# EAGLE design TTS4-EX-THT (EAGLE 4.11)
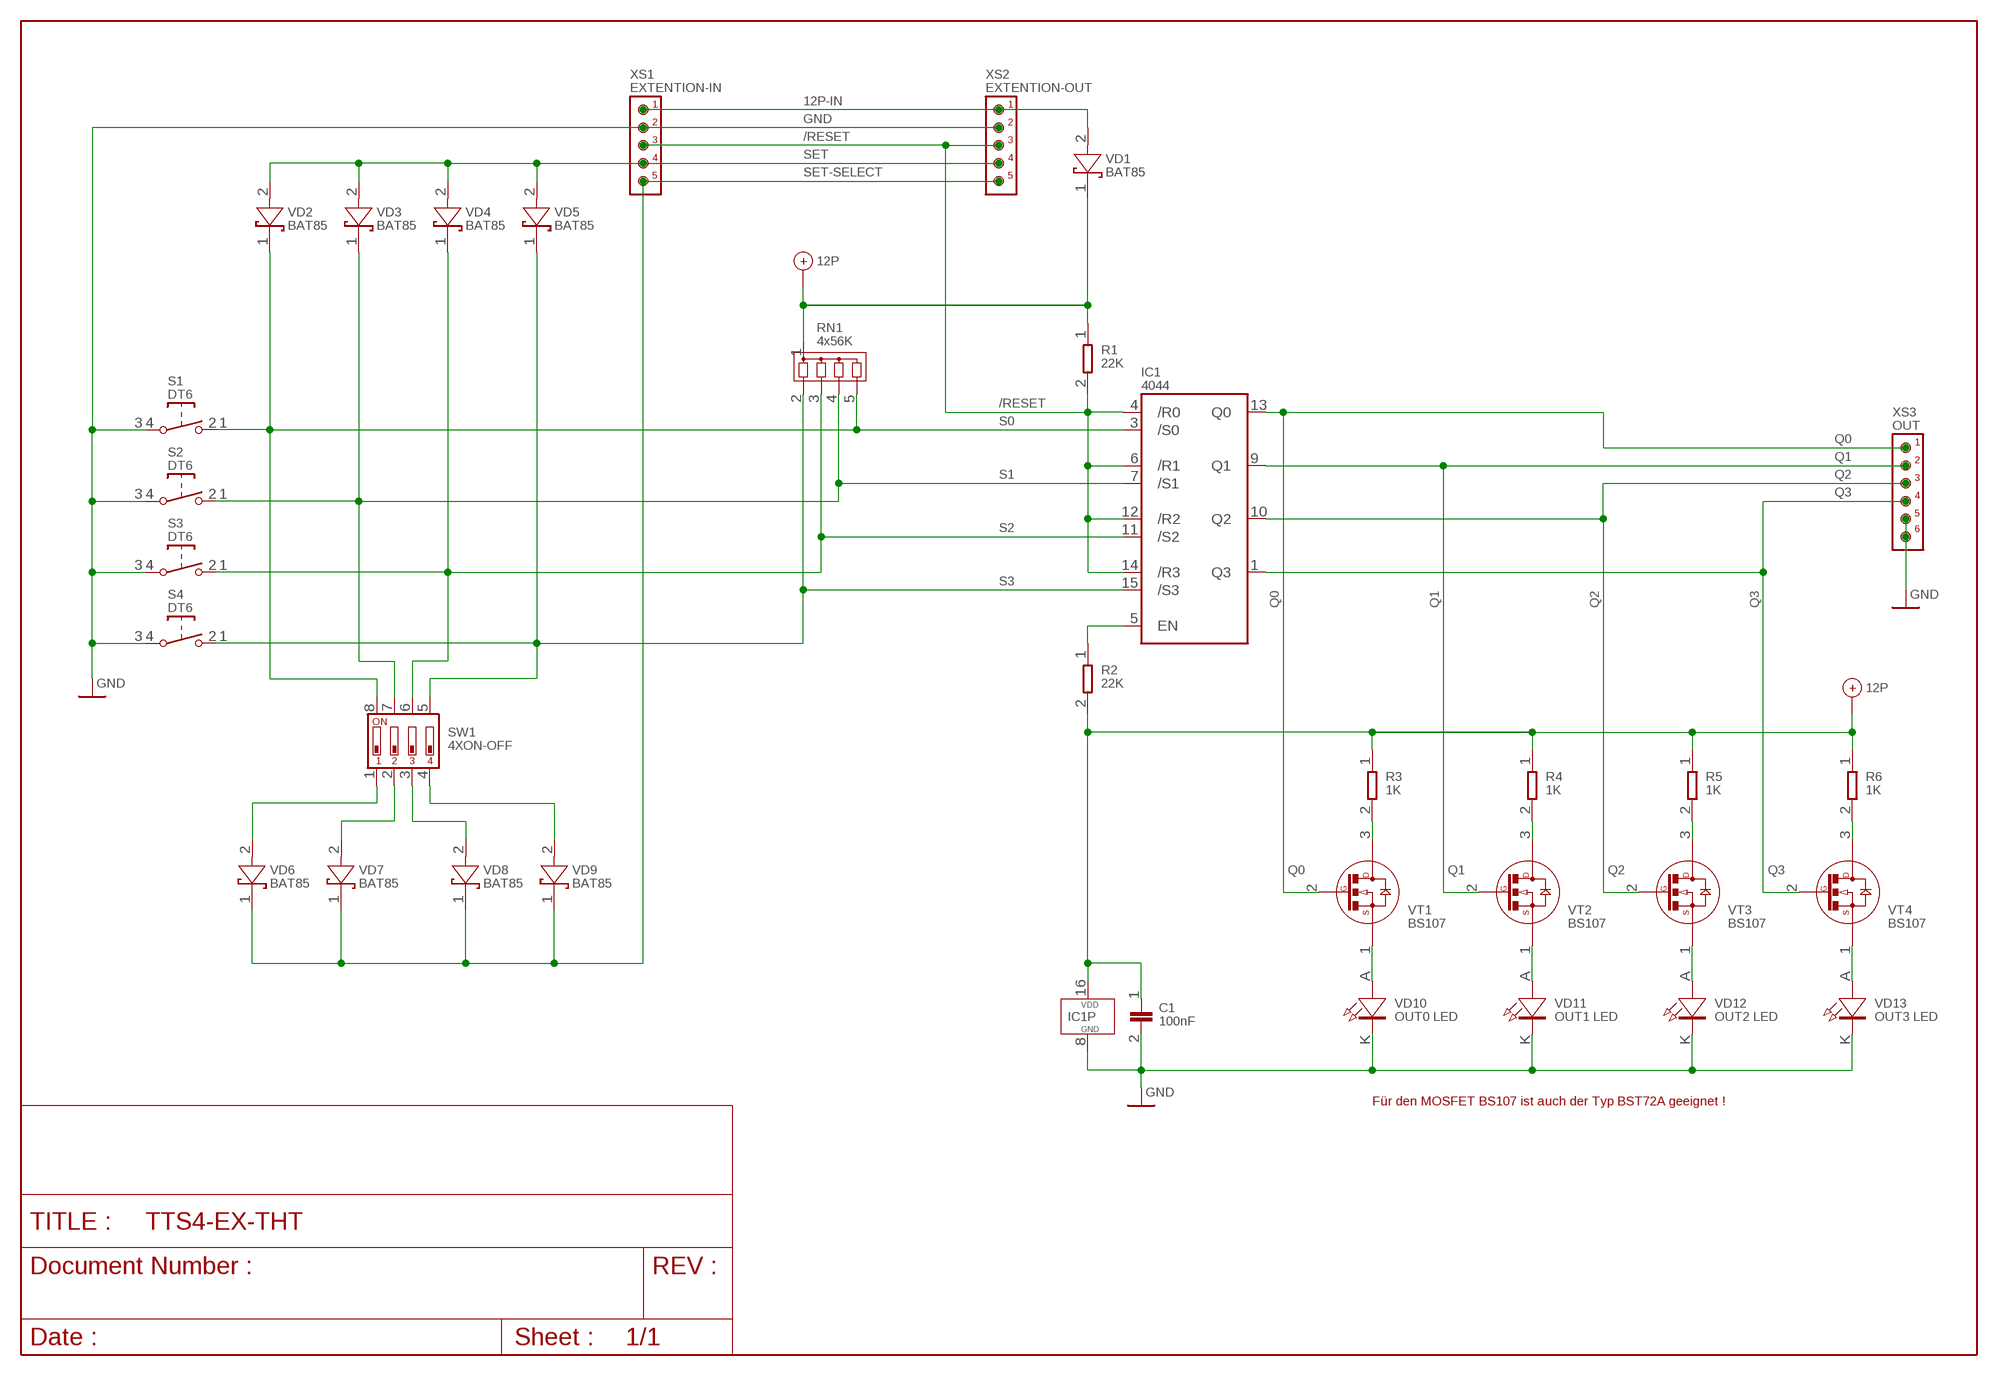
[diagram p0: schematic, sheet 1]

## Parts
C1  100nF  C-5  [C5]
IC1  4044  4044_LP  [DIL16LP]
R1  22K  R0207-12,5  [R0207-12,5]
R2  22K  R0207-12,5  [R0207-12,5]
R3  1K  R0207-12,5  [R0207-12,5]
R4  1K  R0207-12,5  [R0207-12,5]
R5  1K  R0207-12,5  [R0207-12,5]
R6  1K  R0207-12,5  [R0207-12,5]
RN1  4x56K  RN4  [RN4]
S1  DT6  DT6-H  [DT6-HOLE]
S2  DT6  DT6-H  [DT6-HOLE]
S3  DT6  DT6-H  [DT6-HOLE]
S4  DT6  DT6-H  [DT6-HOLE]
SW1  4XON-OFF  SW_DIP-4EPG  [EDG-04]
VD1  BAT85  BAT85-DO  [DO35-10]
VD2  BAT85  BAT85-DO  [DO35-10]
VD3  BAT85  BAT85-DO  [DO35-10]
VD4  BAT85  BAT85-DO  [DO35-10]
VD5  BAT85  BAT85-DO  [DO35-10]
VD6  BAT85  BAT85-DO  [DO35-10]
VD7  BAT85  BAT85-DO  [DO35-10]
VD8  BAT85  BAT85-DO  [DO35-10]
VD9  BAT85  BAT85-DO  [DO35-10]
VD10  OUT0 LED  LED3MM  [LED-3MM]
VD11  OUT1 LED  LED3MM  [LED-3MM]
VD12  OUT2 LED  LED3MM  [LED-3MM]
VD13  OUT3 LED  LED3MM  [LED-3MM]
VT1  BS107  BS107-92A  [TO92A0]
VT2  BS107  BS107-92A  [TO92A0]
VT3  BS107  BS107-92A  [TO92A0]
VT4  BS107  BS107-92A  [TO92A0]
XS1  EXTENTION-IN  PF1X5  [1X5]
XS2  EXTENTION-OUT  PF1X5  [1X5]
XS3  OUT  PF1X6  [1X6]

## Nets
12P: C1.1 IC1.16(VDD) R1.1 R2.2 R3.1 R4.1 R5.1 R6.1 RN1.1 VD1.1(K)
12P-IN: VD1.2(A) XS1.1 XS2.1
/RESET: IC1.4(/R0) IC1.6(/R1) IC1.12(/R2) IC1.14(/R3) R1.2 XS1.3 XS2.3
GND: C1.2 IC1.8(GND) S1.3(P) S1.4(P) S2.3(P) S2.4(P) S3.3(P) S3.4(P) S4.3(P) S4.4(P) VD10.K VD11.K VD12.K VD13.K XS1.2 XS2.2 XS3.5 XS3.6
N$5: VD10.A VT1.1(S)
N$6: VD11.A VT2.1(S)
N$7: VD12.A VT3.1(S)
N$8: VD13.A VT4.1(S)
N$9: IC1.5(EN) R2.1
N$11: R3.2 VT1.3(D)
N$12: R4.2 VT2.3(D)
N$13: R5.2 VT3.3(D)
N$14: R6.2 VT4.3(D)
Q0: IC1.13(Q0) VT1.2(G) XS3.1
Q1: IC1.9(Q1) VT2.2(G) XS3.2
Q2: IC1.10(Q2) VT3.2(G) XS3.3
Q3: IC1.1(Q3) VT4.2(G) XS3.4
S0: IC1.3(/S0) RN1.5 S1.1(S) S1.2(S) SW1.8 VD2.1(K)
S1: IC1.7(/S1) RN1.4 S2.1(S) S2.2(S) SW1.7 VD3.1(K)
S2: IC1.11(/S2) RN1.3 S3.1(S) S3.2(S) SW1.6 VD4.1(K)
S3: IC1.15(/S3) RN1.2 S4.1(S) S4.2(S) SW1.5 VD5.1(K)
SET: VD2.2(A) VD3.2(A) VD4.2(A) VD5.2(A) XS1.4 XS2.4
SET-SELECT: VD6.1(K) VD7.1(K) VD8.1(K) VD9.1(K) XS1.5 XS2.5
SL1: SW1.1 VD6.2(A)
SL2: SW1.2 VD7.2(A)
SL3: SW1.3 VD8.2(A)
SL4: SW1.4 VD9.2(A)

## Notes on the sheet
- Für den MOSFET BS107 ist auch der Typ BST72A geeignet !

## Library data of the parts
C1 = RLC:C-: Kondensator
IC1 = 40XX:4044_: vier RS - Flip - Flop mit Tristate - Ausgängen
R1-R6 = RLC:R: Widerstand
RN1 = RLC:RN4: Widerstandsnetzwerk mit 4 Widerständen , einseitig zusammengeschaltet
S1-S4 = SWITCH:DT: ITT SWITCH
SW1 = DIL - SW:SW_DIP-4
VD1-VD9 = DIODEN:BAT85-: Kleinsignal Schottkydiode
VD10-VD13 = OPTO:LED
VT1-VT4 = TRANS:BS107-: N - Channel Enhancement TMOS - Transistor
XS1 XS2 = PF:PF1X5
XS3 = PF:PF1X6

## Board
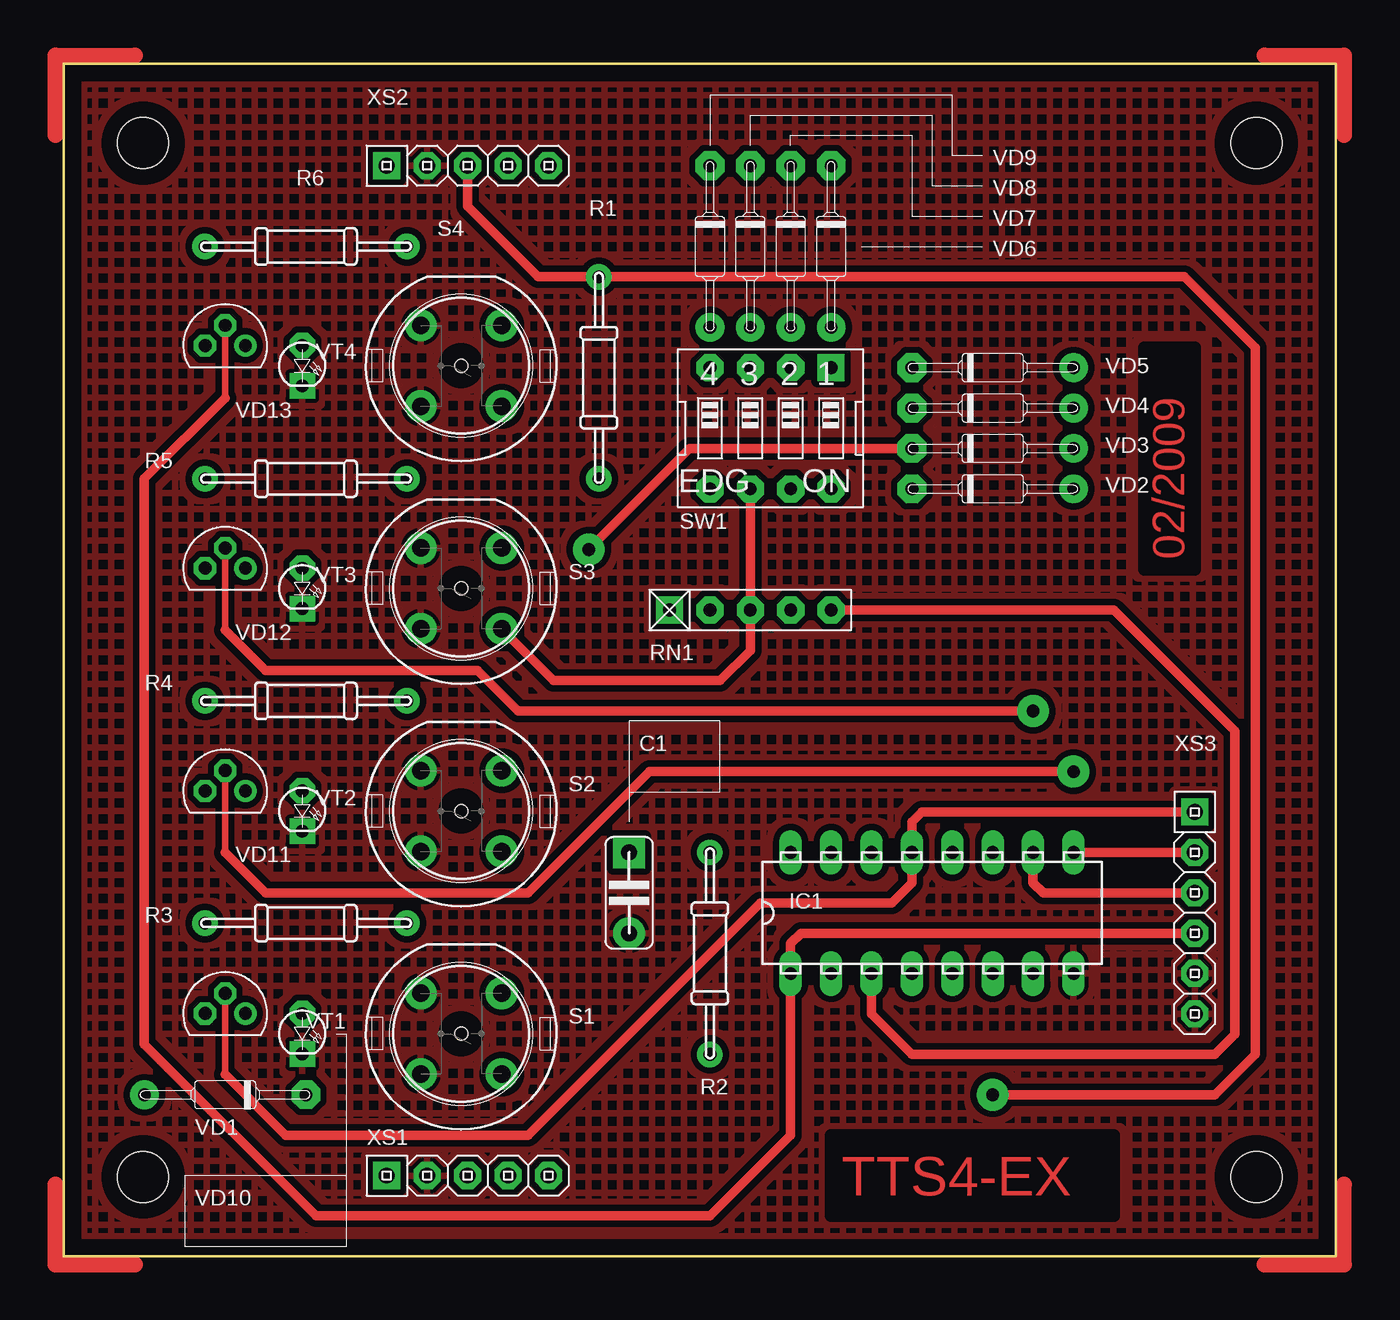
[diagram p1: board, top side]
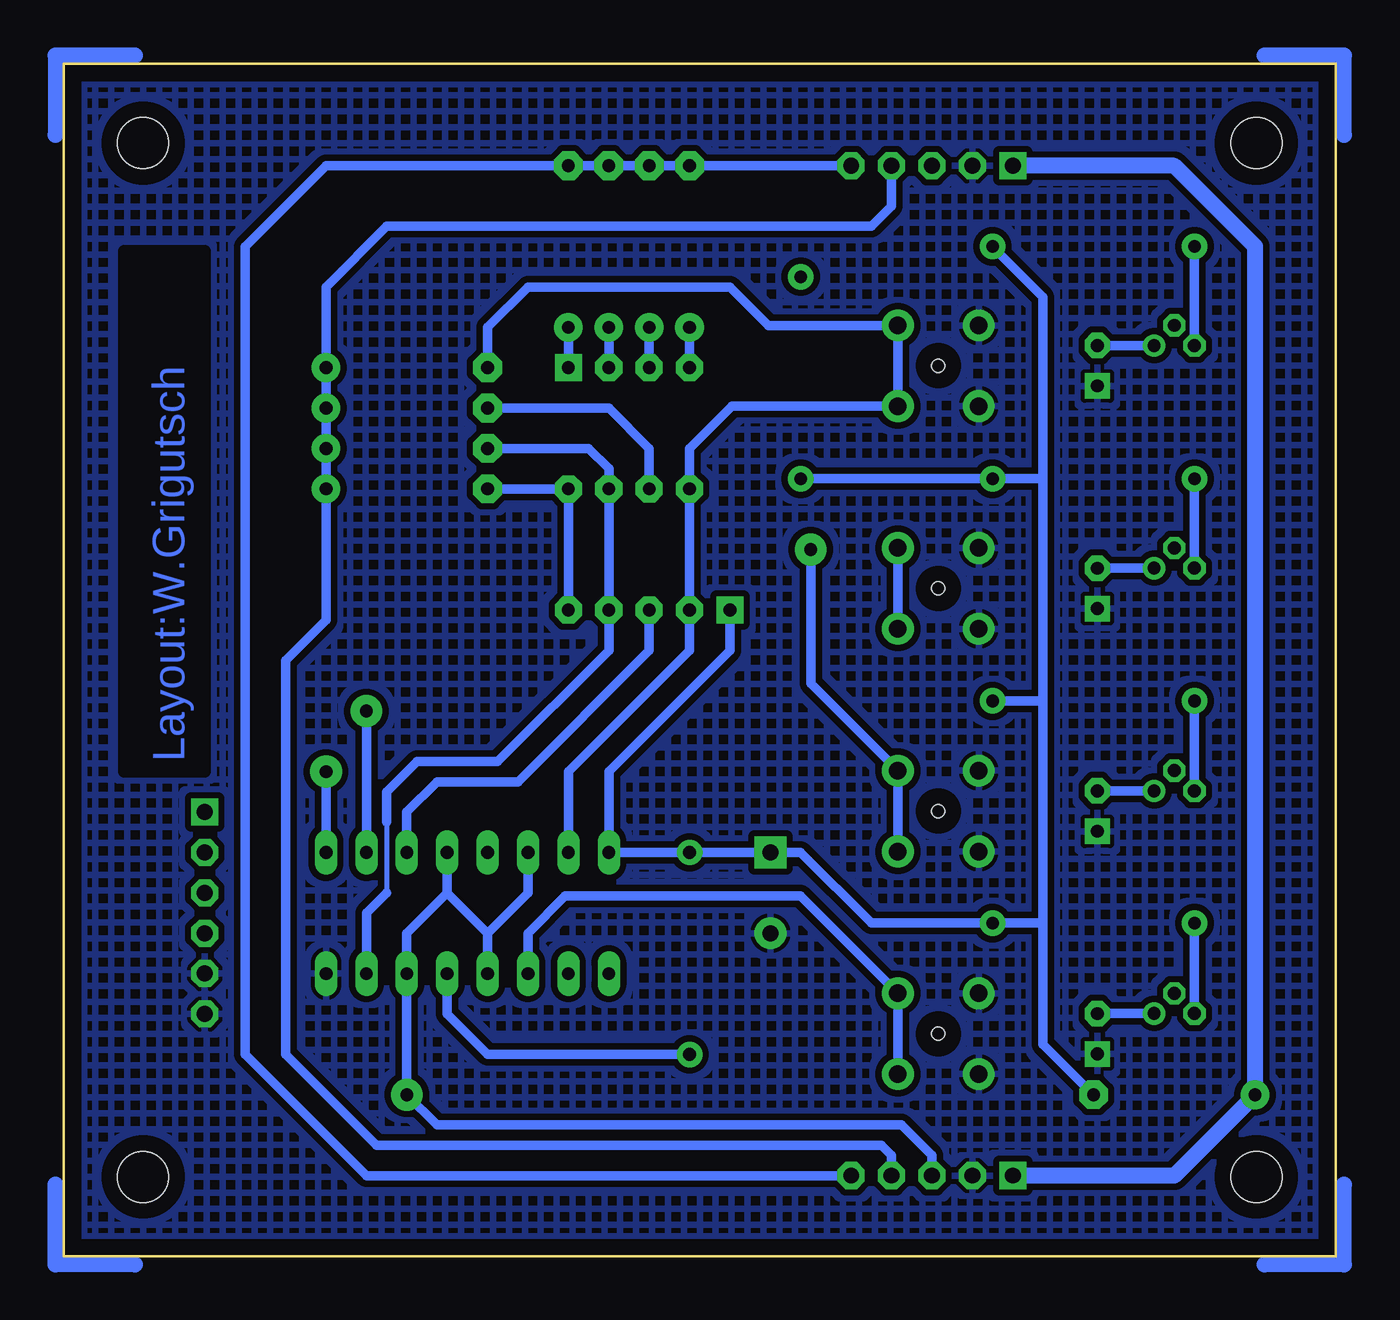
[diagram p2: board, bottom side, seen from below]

Size 80 x 75 mm. Coordinates in mm from the lower left corner, seen from the top.
Outline: 0,0 80,0 80,75 0,75 0,0
Copper layers (1*16): Top 0.035mm / dielectric 1.5mm / Bottom 0.035mm
Design rules "default": minimum track width 6mil, minimum drill 20mil, track to track 6mil, track to pad 6mil, pad to pad 6mil, via to via 10mil, smd to smd 0mil, copper to edge 40mil, drill to drill 8mil, minimum pad ring 10mil, minimum via ring 8mil, stop-mask expansion 4mil, vias tented up to drill 0mil, thermal gap 10mil
Holes 3.2 mm at 5,5 75,5 5,70 75,70
tRestrict: area 48.3,2.5 to 66,7.6; area 67.9,43.2 to 71.1,57.1
bRestrict: area 71.1,30.5 to 76.2,63.2

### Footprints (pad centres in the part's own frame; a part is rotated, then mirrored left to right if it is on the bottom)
C5 = drill 1 pad 2 square: 1 -2.54,0 | drill 1 pad 2 round: 2 2.54,0
DIL16LP = drill 0.8 pad 1.4 long: 1 -8.89,-3.81; 2 -6.35,-3.81; 3 -3.81,-3.81; 4 -1.27,-3.81; 5 1.27,-3.81; 6 3.81,-3.81; 7 6.35,-3.81; 8 8.89,-3.81; 9 8.89,3.81; 10 6.35,3.81; 11 3.81,3.81; 12 1.27,3.81; 13 -1.27,3.81; 14 -3.81,3.81; 15 -6.35,3.81; 16 -8.89,3.81
R0207-12,5 = drill 0.8 pad 1.6 round: 1 -6.35,0; 2 6.35,0
RN4 = drill 0.8 pad 1.7 square: 1 -5.08,0 | drill 0.8 pad 1.7 octagon: 2 -2.54,0; 3 0,0; 4 2.54,0; 5 5.08,0
DT6-HOLE = drill 1.1 pad 2 round: 1 -2.54,2.54; 2 2.54,2.54; 3 2.54,-2.54; 4 -2.54,-2.54 | hole 0.8: 0,0
EDG-04 = drill 0.8 pad 1.7 square: 1 -3.81,-3.81 | drill 0.8 pad 1.7 octagon: 2 -1.27,-3.81; 3 1.27,-3.81; 4 3.81,-3.81; 5 3.81,3.81; 6 1.27,3.81; 7 -1.27,3.81; 8 -3.81,3.81
DO35-10@1 = drill 0.8 pad 1.8 octagon: 1 -5.08,0 | drill 0.8 pad 1.8 round: 2 5.08,0
LED-3MM = drill 0.8 pad 1.6 octagon: A 1.27,0 | drill 0.8 pad 1.6 square: K -1.27,0
TO92A0 = drill 0.813 pad 1.4 round: 1 1.27,0 | drill 0.813 pad 1.4 octagon: 2 0,1.27; 3 -1.27,0
1X5 = drill 1 pad 1.7 square: 1 -5.08,0 | drill 1 pad 1.7 octagon: 2 -2.54,0; 3 0,0; 4 2.54,0; 5 5.08,0
1X6 = drill 1 pad 1.7 square: 1 -6.35,0 | drill 1 pad 1.7 octagon: 2 -3.81,0; 3 -1.27,0; 4 1.27,0; 5 3.81,0; 6 6.35,0

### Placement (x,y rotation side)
C1  35.56,22.86 270 top
IC1  54.61,21.59 0 top
R1  33.66,55.24 90 top
R2  40.64,19.05 90 top
R3  15.24,20.95 180 top
R4  15.24,34.92 180 top
R5  15.24,48.9 180 top
R6  15.24,63.5 180 top
RN1  43.18,40.64 0 top
S1  25,14 270 top
S2  25,28 270 top
S3  25,42 270 top
S4  25,56 270 top
SW1  44.45,52.07 180 top
VD1  BAT85  [DO35-10@1]  10.16,10.16 180 top
VD2  BAT85  [DO35-10@1]  58.42,48.26 0 top
VD3  BAT85  [DO35-10@1]  58.42,50.8 0 top
VD4  BAT85  [DO35-10@1]  58.42,53.34 0 top
VD5  BAT85  [DO35-10@1]  58.42,55.88 0 top
VD6  BAT85  [DO35-10@1]  48.26,63.5 270 top
VD7  BAT85  [DO35-10@1]  45.72,63.5 270 top
VD8  BAT85  [DO35-10@1]  43.18,63.5 270 top
VD9  BAT85  [DO35-10@1]  40.64,63.5 270 top
VD10  15,14 90 top
VD11  15,28 90 top
VD12  15,42 90 top
VD13  15,56 90 top
VT1  10.16,15.27 0 top
VT2  10.16,29.27 0 top
VT3  10.16,43.27 0 top
VT4  10.16,57.27 0 top
XS1  25.4,5.08 0 top
XS2  25.4,68.58 0 top
XS3  71.12,21.59 270 top

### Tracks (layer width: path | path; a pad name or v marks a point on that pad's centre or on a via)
12P
  Bottom 0.6: R6.1 18.41,60.33 18.41,48.9 | 18.41,48.9 R5.1 R1.1 | 18.41,34.92 18.41,48.9 | 18.41,34.92 R4.1 | 18.41,20.95 R3.1 29.21,20.95 33.66,25.4 C1.1 R2.2 IC1.16 45.72,30.48 38.1,38.1 RN1.1 | 18.41,20.95 18.41,34.92 | VD1.1 18.41,13.34 18.41,20.95
12P-IN
  Bottom 1: XS2.1 10.16,68.58 5.08,63.5 VD1.2 10.16,5.08 XS1.1
/RESET  (via drill 0.8 pad 2)
  Top 0.6: XS2.3 25.4,66.04 29.84,61.59 R1.2 70.48,61.59 74.93,57.15 74.93,12.7 72.39,10.16 v58.42,10.16
  Bottom 0.6: 53.34,20.32 IC1.4 | 53.34,20.32 50.8,22.86 IC1.14 | 55.88,22.86 IC1.12 | 55.88,22.86 53.34,20.32 | 55.88,22.86 58.42,20.32 IC1.6 v58.42,10.16 56.52,8.26 27.3,8.26 25.4,6.35 XS1.3
GND
  pour Top (isolate 0.4, hatched): 1,1 1,74 79,74 79,1
  pour Bottom (isolate 0.4, hatched): 1,1 1,74 79,74 79,1
N$1
  Top 1: 4.5,-0.5 -0.5,-0.5 -0.5,4.5
N$2
  Top 1: 75.5,-0.5 80.5,-0.5 80.5,4.5
N$3
  Top 1: 4.5,75.5 -0.5,75.5 -0.5,70.5
N$4
  Top 1: 80.5,70.5 80.5,75.5 75.5,75.5
N$5
  Bottom 0.6: VT1.1 VD10.A
N$6
  Bottom 0.6: VT2.1 VD11.A
N$7
  Bottom 0.6: VT3.1 VD12.A
N$8
  Bottom 0.6: VT4.1 VD13.A
N$9
  Bottom 0.6: R2.1 53.34,12.7 55.88,15.24 IC1.5
N$10
  Bottom 1: 4.5,-0.5 -0.5,-0.5 -0.5,4.5
N$11
  Bottom 0.6: VT1.3 R3.2
N$12
  Bottom 0.6: VT2.3 R4.2
N$13
  Bottom 0.6: VT3.3 R5.2
N$14
  Bottom 0.6: VT4.3 R6.2
N$15
  Bottom 1: 75.5,-0.5 80.5,-0.5 80.5,4.5
N$16
  Bottom 1: 4.5,75.5 -0.5,75.5 -0.5,70.5
N$17
  Bottom 1: 80.5,70.5 80.5,75.5 75.5,75.5
Q0
  Top 0.4: 10.16,11.43 VT1.2
  Top 0.6: XS3.1 53.98,27.94 53.34,27.3 IC1.13 53.34,23.5 52.07,22.23 43.81,22.23 29.21,7.62 13.97,7.62 10.16,11.43
Q1  (via drill 0.8 pad 2)
  Top 0.4: 10.16,25.4 VT2.2
  Top 0.6: IC1.9 XS3.2 | 10.16,25.4 12.7,22.86 29.21,22.86 36.83,30.48 v63.5,30.48
  Bottom 0.6: v63.5,30.48 IC1.9
Q2  (via drill 0.8 pad 2)
  Top 0.4: 10.16,39.37 VT3.2
  Top 0.6: XS3.3 61.59,22.86 60.96,23.5 IC1.10 | 10.16,39.37 12.7,36.83 26.04,36.83 28.57,34.29 v60.96,34.29
  Bottom 0.6: v60.96,34.29 IC1.10
Q3
  Top 0.4: 10.16,53.98 VT4.2
  Top 0.6: XS3.4 46.35,20.32 45.72,19.68 IC1.1 45.72,7.62 40.64,2.54 15.88,2.54 5.08,13.34 5.08,48.9 10.16,53.98
S0
  Top 0.6: RN1.5 66.04,40.64 73.66,33.02 73.66,13.97 72.39,12.7 53.34,12.7 50.8,15.24 IC1.3
  Bottom 0.6: S1.2 S1.1 33.66,22.66 48.47,22.66 50.8,20.32 IC1.3 | RN1.5 SW1.8 VD2.1
S1  (via drill 0.8 pad 2)
  Top 0.6: v33.02,44.45 39.37,50.8 VD3.1
  Bottom 0.3: 59.69,27.3 59.69,22.86
  Bottom 0.6: S2.2 S2.1 33.02,36.02 v33.02,44.45 | VD3.1 46.99,50.8 45.72,49.53 SW1.7 RN1.4 45.72,38.1 52.7,31.11 57.78,31.11 59.69,29.21 59.69,27.3 | IC1.7 60.96,21.59 59.69,22.86
S2
  Top 0.6: SW1.6 RN1.3 43.18,38.1 41.27,36.2 30.8,36.2 S3.2
  Bottom 0.6: S3.2 S3.1 | RN1.3 43.18,38.1 51.44,29.84 56.52,29.84 58.42,27.94 IC1.11 | SW1.6 43.18,50.8 45.72,53.34 VD4.1
S3
  Bottom 0.6: IC1.15 48.26,30.48 40.64,38.1 RN1.2 SW1.5 40.64,50.8 37.98,53.46 S4.2 S4.1 35.68,58.54 38.1,60.96 50.8,60.96 53.34,58.42 VD5.1
SET
  Bottom 0.6: XS2.4 27.94,66.04 29.21,64.77 59.69,64.77 63.5,60.96 VD5.2 VD4.2 VD3.2 VD2.2 63.5,40.01 66.04,37.47 66.04,12.7 60.33,6.99 28.57,6.99 27.94,6.35 XS1.4
SET-SELECT
  Bottom 0.6: XS2.5 VD9.1 VD8.1 VD7.1 VD6.1 63.5,68.58 68.58,63.5 68.58,12.7 60.96,5.08 XS1.5
SL1
  Bottom 0.6: SW1.1 VD6.2
SL2
  Bottom 0.6: SW1.2 VD7.2
SL3
  Bottom 0.6: SW1.3 VD8.2
SL4
  Bottom 0.6: SW1.4 VD9.2

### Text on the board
Top: 02/2009 | TTS4-EX
Bottom: Layout:W.Grigutsch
